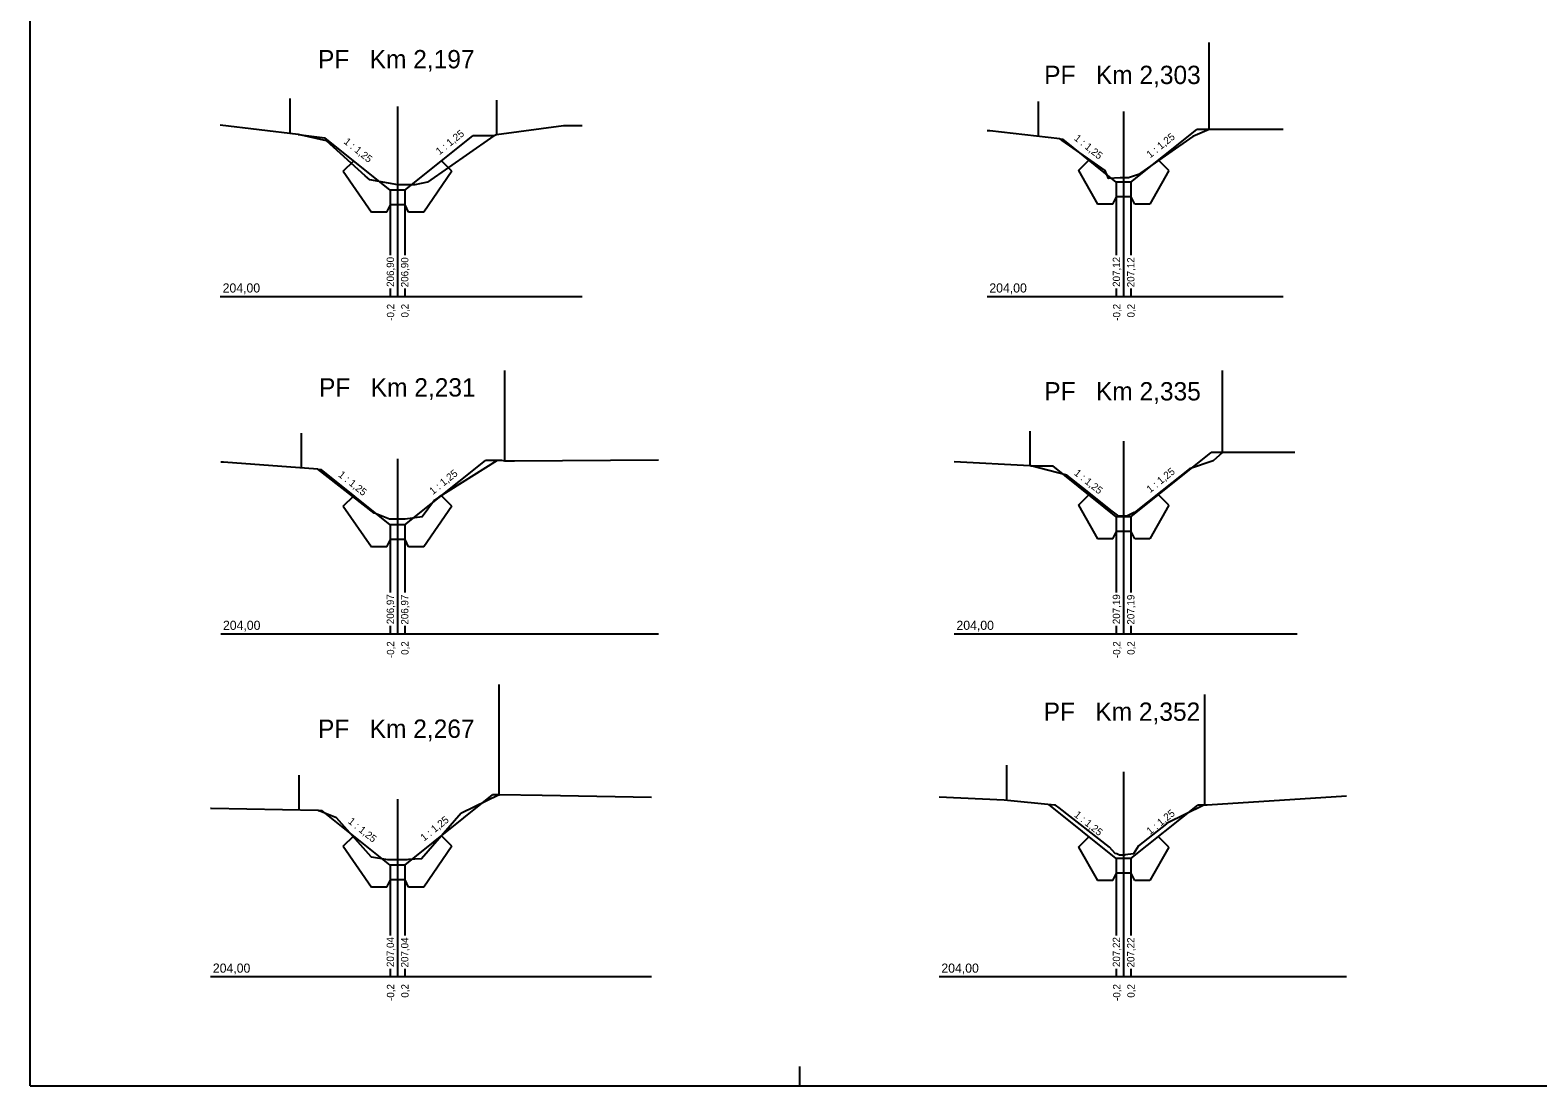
# Model space of a CAD drawing. Extents: x -547174 to -543113, y -1125006 to -1123643.
# Drawn here: x -547152.27 to -547111.11, y -1123903.94 to -1123875.1 of the extents above; entities that cross this region are included whole.
import ezdxf

# ---------------------------------------------------------------- set-up
doc = ezdxf.new("R2010")
doc.units = 0
for name, color, linetype in [('Default', 7, 'Continuous'), ('Profile', 7, 'Continuous'), ('PROFILY NÁVRH', 7, 'Continuous'), ('Section', 7, 'Continuous'), ('STANIČENÍ', 7, 'Continuous')]:
    doc.layers.add(name, color=color, linetype=linetype)

msp = doc.modelspace()

# ---------------------------------------------------------------- linework, layer by layer
at = {"layer": 'Default'}
for points in [[(-547137.203, -1123877.715), (-547137.71, -1123877.715), (-547139.543, -1123877.966), (-547139.617, -1123877.987), (-547139.708, -1123878.054), (-547141.425, -1123879.254), (-547141.425, -1123879.254), (-547141.773, -1123879.333), (-547141.782, -1123879.334), (-547141.984, -1123879.334), (-547141.988, -1123879.334), (-547141.992, -1123879.334), (-547142.236, -1123879.334), (-547142.997, -1123879.196), (-547142.999, -1123879.196), (-547143.122, -1123879.085), (-547144.18, -1123878.126), (-547144.947, -1123877.956), (-547144.953, -1123877.955), (-547147.081, -1123877.696)], [(-547118.065, -1123877.816), (-547120.083, -1123877.816), (-547120.529, -1123878.013), (-547120.534, -1123878.013), (-547121.954, -1123879.005), (-547122.016, -1123879.046), (-547122.287, -1123879.135), (-547122.289, -1123879.136), (-547122.398, -1123879.136), (-547122.399, -1123879.136), (-547122.4, -1123879.136), (-547122.517, -1123879.136), (-547122.519, -1123879.135), (-547122.832, -1123879.154), (-547122.833, -1123879.154), (-547122.925, -1123878.942), (-547124.096, -1123878.122), (-547124.141, -1123878.085), (-547124.159, -1123878.081), (-547124.164, -1123878.077), (-547124.164, -1123878.076), (-547126.073, -1123877.855), (-547126.149, -1123877.853)], [(-547135.116, -1123886.85), (-547139.05, -1123886.874), (-547139.314, -1123886.874), (-547139.4, -1123886.86), (-547139.521, -1123886.856), (-547141.115, -1123887.861), (-547141.23, -1123887.942), (-547141.571, -1123888.4), (-547141.571, -1123888.4), (-547141.573, -1123888.4), (-547142.037, -1123888.46), (-547142.039, -1123888.46), (-547142.25, -1123888.46), (-547142.455, -1123888.46), (-547142.457, -1123888.46), (-547142.463, -1123888.459), (-547142.876, -1123888.301), (-547142.882, -1123888.299), (-547142.882, -1123888.299), (-547144.421, -1123887.098), (-547146.995, -1123886.904), (-547147.071, -1123886.9)], [(-547117.745, -1123886.641), (-547119.723, -1123886.64), (-547119.723, -1123886.64), (-547119.977, -1123886.863), (-547120.619, -1123887.088), (-547121.369, -1123887.678), (-547122.128, -1123888.275), (-547122.134, -1123888.279), (-547122.134, -1123888.279), (-547122.337, -1123888.379), (-547122.338, -1123888.379), (-547122.442, -1123888.379), (-547122.553, -1123888.379), (-547122.553, -1123888.379), (-547122.729, -1123888.239), (-547122.73, -1123888.239), (-547122.73, -1123888.239), (-547123.542, -1123887.596), (-547123.968, -1123887.258), (-547124.951, -1123887.008), (-547124.965, -1123887.007), (-547124.984, -1123887.006), (-547127.047, -1123886.893)], [(-547135.314, -1123896.061), (-547138.298, -1123896.008), (-547139.466, -1123895.992), (-547139.466, -1123895.994), (-547139.466, -1123895.993), (-547140.499, -1123896.491), (-547140.499, -1123896.491), (-547140.501, -1123896.492), (-547140.502, -1123896.493), (-547141.585, -1123897.733), (-547141.939, -1123897.758), (-547141.991, -1123897.762), (-547141.993, -1123897.762), (-547141.993, -1123897.762), (-547142.259, -1123897.762), (-547142.259, -1123897.762), (-547142.507, -1123897.762), (-547142.508, -1123897.762), (-547142.95, -1123897.692), (-547142.95, -1123897.692), (-547142.96, -1123897.684), (-547143.913, -1123896.621), (-547144.414, -1123896.414), (-547147.329, -1123896.364), (-547147.348, -1123896.363)], [(-547116.332, -1123896.028), (-547120.143, -1123896.268), (-547120.207, -1123896.267), (-547120.228, -1123896.273), (-547121.233, -1123896.767), (-547121.243, -1123896.774), (-547121.252, -1123896.782), (-547122.014, -1123897.384), (-547122.152, -1123897.602), (-547122.376, -1123897.632), (-547122.378, -1123897.633), (-547122.379, -1123897.633), (-547122.456, -1123897.633), (-547122.529, -1123897.633), (-547122.53, -1123897.633), (-547122.61, -1123897.605), (-547122.651, -1123897.592), (-547122.651, -1123897.592), (-547122.807, -1123897.422), (-547124.179, -1123896.348), (-547124.276, -1123896.272), (-547124.276, -1123896.272), (-547124.277, -1123896.272), (-547124.31, -1123896.269), (-547125.679, -1123896.131), (-547127.459, -1123896.05)]]:
    msp.add_lwpolyline(points, dxfattribs=at)
at = {"layer": 'Profile'}
for p, q in [((-547152.272, -1123903.937), (-547152.272, -1123874.237)), ((-547131.272, -1123903.409), (-547131.272, -1123903.937)), ((-547152.272, -1123903.937), (-547131.272, -1123903.937)), ((-547131.272, -1123903.937), (-547110.272, -1123903.937))]:
    msp.add_line(p, q, dxfattribs=at)
at = {"layer": 'PROFILY NÁVRH'}
for p, q in [((-547145.183, -1123876.976), (-547145.183, -1123877.927)), ((-547139.543, -1123877.015), (-547139.543, -1123877.966)), ((-547124.751, -1123877.057), (-547124.751, -1123878.008)), ((-547122.221, -1123879.256), (-547120.426, -1123877.816)), ((-547120.083, -1123877.816), (-547120.426, -1123877.816)), ((-547144.953, -1123877.955), (-547144.228, -1123878.044)), ((-547142.443, -1123879.476), (-547144.228, -1123878.044)), ((-547142.043, -1123879.476), (-547140.188, -1123877.987)), ((-547139.617, -1123877.987), (-547140.188, -1123877.987)), ((-547124.164, -1123878.076), (-547124.079, -1123878.086)), ((-547122.621, -1123879.256), (-547124.079, -1123878.086)), ((-547143.723, -1123878.959), (-547143.44, -1123878.676)), ((-547140.763, -1123878.959), (-547141.046, -1123878.676)), ((-547123.651, -1123878.939), (-547123.369, -1123878.656)), ((-547121.19, -1123878.939), (-547121.473, -1123878.656)), ((-547143.723, -1123878.959), (-547142.958, -1123880.076)), ((-547140.763, -1123878.959), (-547141.528, -1123880.076)), ((-547123.651, -1123878.939), (-547123.136, -1123879.856)), ((-547121.19, -1123878.939), (-547121.706, -1123879.856)), ((-547142.043, -1123879.476), (-547142.443, -1123879.476)), ((-547142.443, -1123879.476), (-547142.443, -1123881.252)), ((-547142.093, -1123879.476), (-547142.393, -1123879.476)), ((-547142.043, -1123879.476), (-547142.343, -1123879.476)), ((-547142.043, -1123879.476), (-547142.043, -1123881.252)), ((-547122.221, -1123879.256), (-547122.621, -1123879.256)), ((-547122.621, -1123879.256), (-547122.621, -1123881.252)), ((-547122.271, -1123879.256), (-547122.571, -1123879.256)), ((-547122.271, -1123879.256), (-547122.571, -1123879.256)), ((-547122.271, -1123879.256), (-547122.571, -1123879.256)), ((-547122.221, -1123879.256), (-547122.521, -1123879.256)), ((-547122.221, -1123879.256), (-547122.221, -1123881.252)), ((-547142.539, -1123880.076), (-547142.439, -1123879.876)), ((-547142.039, -1123879.876), (-547142.439, -1123879.876)), ((-547141.939, -1123880.076), (-547142.039, -1123879.876)), ((-547122.717, -1123879.856), (-547123.136, -1123879.856)), ((-547122.717, -1123879.856), (-547122.617, -1123879.656)), ((-547122.217, -1123879.656), (-547122.617, -1123879.656)), ((-547122.117, -1123879.856), (-547122.217, -1123879.656)), ((-547121.706, -1123879.856), (-547122.117, -1123879.856)), ((-547142.539, -1123880.076), (-547142.958, -1123880.076)), ((-547141.528, -1123880.076), (-547141.939, -1123880.076)), ((-547142.443, -1123882.164), (-547142.443, -1123882.376)), ((-547142.043, -1123882.164), (-547142.043, -1123882.376)), ((-547122.621, -1123882.164), (-547122.621, -1123882.376)), ((-547122.221, -1123882.164), (-547122.221, -1123882.376)), ((-547144.873, -1123886.113), (-547144.873, -1123887.064)), ((-547124.981, -1123886.055), (-547124.981, -1123887.006)), ((-547142.043, -1123888.619), (-547139.845, -1123886.856)), ((-547139.521, -1123886.856), (-547139.845, -1123886.856)), ((-547122.221, -1123888.399), (-547120.028, -1123886.64)), ((-547119.723, -1123886.64), (-547120.028, -1123886.64)), ((-547144.421, -1123887.098), (-547144.329, -1123887.105)), ((-547142.443, -1123888.619), (-547144.329, -1123887.105)), ((-547124.951, -1123887.008), (-547124.354, -1123887.008)), ((-547122.621, -1123888.399), (-547124.354, -1123887.008)), ((-547143.723, -1123888.102), (-547143.44, -1123887.819)), ((-547143.723, -1123888.102), (-547142.958, -1123889.219)), ((-547140.763, -1123888.102), (-547141.528, -1123889.219)), ((-547140.763, -1123888.102), (-547141.046, -1123887.819)), ((-547123.651, -1123888.082), (-547123.369, -1123887.799)), ((-547123.651, -1123888.082), (-547123.136, -1123888.999)), ((-547121.19, -1123888.082), (-547121.706, -1123888.999)), ((-547121.19, -1123888.082), (-547121.473, -1123887.799)), ((-547122.221, -1123888.399), (-547122.621, -1123888.399)), ((-547122.621, -1123888.399), (-547122.621, -1123890.465)), ((-547122.271, -1123888.399), (-547122.571, -1123888.399)), ((-547122.271, -1123888.399), (-547122.571, -1123888.399)), ((-547122.271, -1123888.399), (-547122.571, -1123888.399)), ((-547122.271, -1123888.399), (-547122.571, -1123888.399)), ((-547122.221, -1123888.399), (-547122.521, -1123888.399)), ((-547122.221, -1123888.399), (-547122.221, -1123890.465)), ((-547142.539, -1123889.219), (-547142.439, -1123889.019)), ((-547142.043, -1123888.619), (-547142.443, -1123888.619)), ((-547142.443, -1123888.619), (-547142.443, -1123890.465)), ((-547142.039, -1123889.019), (-547142.439, -1123889.019)), ((-547142.093, -1123888.619), (-547142.393, -1123888.619)), ((-547142.093, -1123888.619), (-547142.393, -1123888.619)), ((-547142.043, -1123888.619), (-547142.343, -1123888.619)), ((-547142.043, -1123888.619), (-547142.043, -1123890.465)), ((-547141.939, -1123889.219), (-547142.039, -1123889.019)), ((-547122.717, -1123888.999), (-547123.136, -1123888.999)), ((-547122.717, -1123888.999), (-547122.617, -1123888.799)), ((-547122.217, -1123888.799), (-547122.617, -1123888.799)), ((-547122.117, -1123888.999), (-547122.217, -1123888.799)), ((-547121.706, -1123888.999), (-547122.117, -1123888.999)), ((-547142.539, -1123889.219), (-547142.958, -1123889.219)), ((-547141.528, -1123889.219), (-547141.939, -1123889.219)), ((-547142.443, -1123891.377), (-547142.443, -1123891.589)), ((-547142.043, -1123891.377), (-547142.043, -1123891.589)), ((-547122.621, -1123891.377), (-547122.621, -1123891.589)), ((-547122.221, -1123891.377), (-547122.221, -1123891.589)), ((-547125.621, -1123895.183), (-547125.621, -1123896.134)), ((-547144.933, -1123895.454), (-547144.933, -1123896.405)), ((-547142.043, -1123897.912), (-547139.65, -1123895.992)), ((-547139.466, -1123895.992), (-547139.65, -1123895.992)), ((-547144.414, -1123896.414), (-547144.308, -1123896.416)), ((-547142.443, -1123897.912), (-547144.308, -1123896.416)), ((-547122.621, -1123897.732), (-547124.464, -1123896.253)), ((-547122.221, -1123897.732), (-547120.395, -1123896.267)), ((-547120.207, -1123896.267), (-547120.395, -1123896.267)), ((-547143.723, -1123897.395), (-547143.44, -1123897.112)), ((-547140.763, -1123897.395), (-547141.046, -1123897.112)), ((-547123.651, -1123897.415), (-547123.369, -1123897.132)), ((-547121.19, -1123897.415), (-547121.473, -1123897.132)), ((-547143.723, -1123897.395), (-547142.958, -1123898.512)), ((-547140.763, -1123897.395), (-547141.528, -1123898.512)), ((-547123.651, -1123897.415), (-547123.136, -1123898.332)), ((-547121.19, -1123897.415), (-547121.706, -1123898.332)), ((-547142.043, -1123897.912), (-547142.443, -1123897.912)), ((-547142.443, -1123897.912), (-547142.443, -1123899.828)), ((-547142.093, -1123897.912), (-547142.393, -1123897.912)), ((-547142.093, -1123897.912), (-547142.393, -1123897.912)), ((-547142.093, -1123897.912), (-547142.393, -1123897.912)), ((-547142.043, -1123897.912), (-547142.343, -1123897.912)), ((-547142.043, -1123897.912), (-547142.043, -1123899.828)), ((-547122.221, -1123897.732), (-547122.621, -1123897.732)), ((-547122.621, -1123897.732), (-547122.621, -1123899.828)), ((-547122.221, -1123897.732), (-547122.221, -1123899.828)), ((-547142.539, -1123898.512), (-547142.439, -1123898.312)), ((-547142.039, -1123898.312), (-547142.439, -1123898.312)), ((-547141.939, -1123898.512), (-547142.039, -1123898.312)), ((-547122.717, -1123898.332), (-547123.136, -1123898.332)), ((-547122.717, -1123898.332), (-547122.617, -1123898.132)), ((-547122.217, -1123898.132), (-547122.617, -1123898.132)), ((-547122.117, -1123898.332), (-547122.217, -1123898.132)), ((-547121.706, -1123898.332), (-547122.117, -1123898.332)), ((-547142.539, -1123898.512), (-547142.958, -1123898.512)), ((-547141.528, -1123898.512), (-547141.939, -1123898.512)), ((-547142.443, -1123900.74), (-547142.443, -1123900.952)), ((-547142.043, -1123900.74), (-547142.043, -1123900.952)), ((-547122.621, -1123900.74), (-547122.621, -1123900.952)), ((-547122.221, -1123900.74), (-547122.221, -1123900.952))]:
    msp.add_line(p, q, dxfattribs=at)
at = {"layer": 'Section'}
for p, q in [((-547142.243, -1123877.188), (-547142.243, -1123882.376)), ((-547122.421, -1123877.325), (-547122.421, -1123882.376)), ((-547147.081, -1123882.376), (-547137.203, -1123882.376)), ((-547126.149, -1123882.376), (-547118.065, -1123882.376)), ((-547122.421, -1123886.332), (-547122.421, -1123891.589)), ((-547142.243, -1123886.809), (-547142.243, -1123891.589)), ((-547147.071, -1123891.589), (-547135.116, -1123891.589)), ((-547127.047, -1123891.589), (-547117.68, -1123891.589)), ((-547122.421, -1123895.357), (-547122.421, -1123900.952)), ((-547142.243, -1123896.104), (-547142.243, -1123900.952)), ((-547147.348, -1123900.952), (-547135.314, -1123900.952)), ((-547127.459, -1123900.952), (-547116.332, -1123900.952))]:
    msp.add_line(p, q, dxfattribs=at)
at = {"layer": 'STANIČENÍ'}
for p, q in [((-547120.083, -1123877.816), (-547120.083, -1123875.444)), ((-547139.314, -1123886.874), (-547139.314, -1123884.399)), ((-547119.723, -1123886.64), (-547119.723, -1123884.399)), ((-547139.466, -1123895.992), (-547139.466, -1123892.977)), ((-547120.207, -1123896.267), (-547120.207, -1123893.252))]:
    msp.add_line(p, q, dxfattribs=at)

# ---------------------------------------------------------------- texts
at = {"layer": 'PROFILY NÁVRH'}
for s, rotation, p in [('1 : 1,25', 38.7413, (-547141.098, -1123878.523)), ('1 : 1,25', 38.7413, (-547121.696, -1123878.61)), ('1 : 1,25', 321.2587, (-547143.727, -1123878.181)), ('1 : 1,25', 321.2587, (-547123.789, -1123878.089)), ('206,90', 90, (-547142.339, -1123882.116)), ('206,90', 90, (-547141.948, -1123882.127)), ('207,12', 90, (-547122.517, -1123882.116)), ('207,12', 90, (-547122.125, -1123882.127)), ('-0,2', 90, (-547142.334, -1123883.042)), ('0,2', 90, (-547141.942, -1123882.953)), ('-0,2', 90, (-547122.511, -1123883.042)), ('0,2', 90, (-547122.12, -1123882.953)), ('1 : 1,25', 321.2587, (-547143.878, -1123887.279)), ('1 : 1,25', 38.7413, (-547141.277, -1123887.803)), ('1 : 1,25', 321.2587, (-547123.789, -1123887.232)), ('1 : 1,25', 38.7413, (-547121.696, -1123887.753)), ('206,97', 90, (-547142.339, -1123891.329)), ('206,97', 90, (-547141.948, -1123891.34)), ('207,19', 90, (-547122.517, -1123891.329)), ('207,19', 90, (-547122.125, -1123891.34)), ('-0,2', 90, (-547142.334, -1123892.255)), ('0,2', 90, (-547141.942, -1123892.166)), ('-0,2', 90, (-547122.511, -1123892.255)), ('0,2', 90, (-547122.12, -1123892.166)), ('1 : 1,25', 38.7413, (-547121.696, -1123897.086)), ('1 : 1,25', 321.2587, (-547143.611, -1123896.745)), ('1 : 1,25', 38.7413, (-547141.518, -1123897.266)), ('1 : 1,25', 321.2587, (-547123.789, -1123896.565)), ('207,04', 90, (-547142.339, -1123900.692)), ('207,04', 90, (-547141.948, -1123900.703)), ('207,22', 90, (-547122.517, -1123900.692)), ('207,22', 90, (-547122.125, -1123900.703)), ('-0,2', 90, (-547142.334, -1123901.618)), ('0,2', 90, (-547141.942, -1123901.529)), ('-0,2', 90, (-547122.511, -1123901.618)), ('0,2', 90, (-547122.12, -1123901.529))]:
    msp.add_text(s, height=0.2, rotation=rotation, dxfattribs=at).set_placement(p)
at = {"layer": 'Section'}
for s, height, p in [('PF   Km 2,197', 0.5, (-547144.414, -1123876.148)), ('PF   Km 2,303', 0.5, (-547124.589, -1123876.577)), ('204,00', 0.25, (-547147.017, -1123882.271)), ('204,00', 0.25, (-547126.086, -1123882.271)), ('PF   Km 2,231', 0.5, (-547144.385, -1123885.111)), ('PF   Km 2,335', 0.5, (-547124.587, -1123885.218)), ('204,00', 0.25, (-547147.008, -1123891.484)), ('204,00', 0.25, (-547126.984, -1123891.484)), ('PF   Km 2,352', 0.5, (-547124.603, -1123893.968)), ('PF   Km 2,267', 0.5, (-547144.414, -1123894.433)), ('204,00', 0.25, (-547147.284, -1123900.847)), ('204,00', 0.25, (-547127.396, -1123900.847))]:
    msp.add_text(s, height=height, dxfattribs=at).set_placement(p)

doc.saveas('drawing.dxf')
